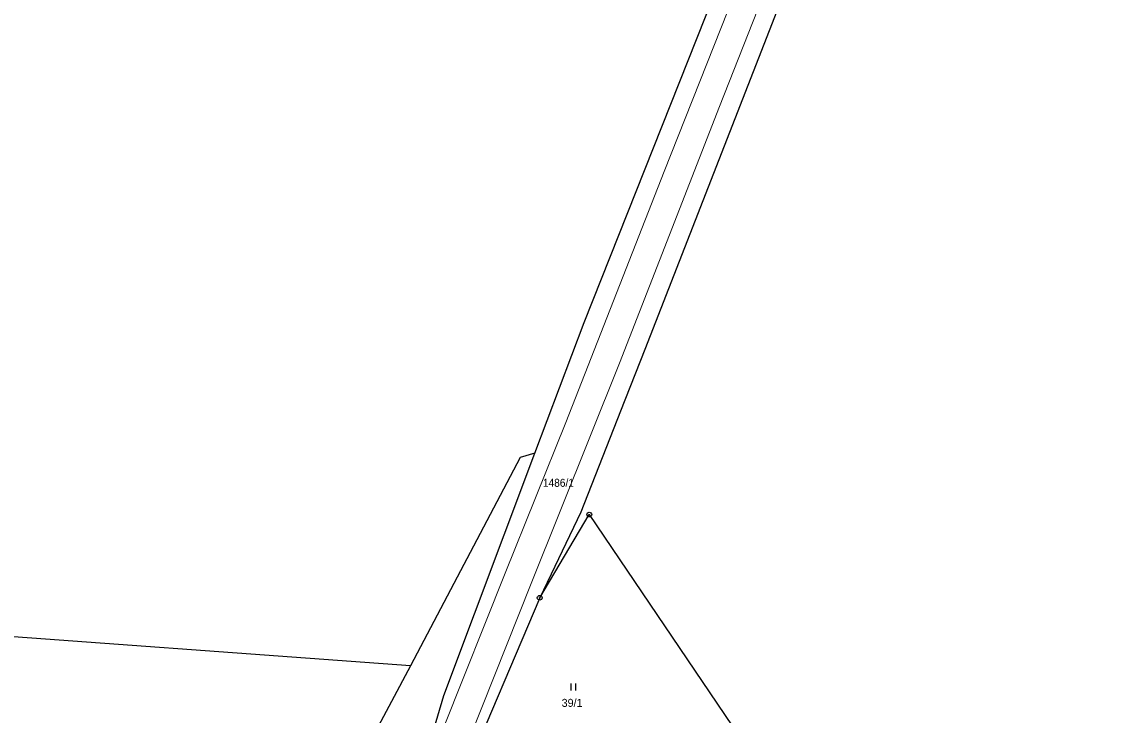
# Model space of a CAD drawing. Extents: x -872229 to -869198, y -1075981 to -1074329.
# Drawn here: x -871207 to -870978.1, y -1075083.8 to -1074936.4 of the extents above; entities that cross this region are included whole.
import ezdxf
from ezdxf.enums import TextEntityAlignment as Align

# ---------------------------------------------------------------- set-up
doc = ezdxf.new("R2010")
doc.units = 0
doc.header["$LTSCALE"] = 0.68
for name, color, linetype, lineweight in [('1', 7, 'Continuous', 25), ('3', 7, 'Continuous', 25), ('4', 7, 'Continuous', 13), ('8', 7, 'Continuous', 25)]:
    doc.layers.add(name, color=color, linetype=linetype, lineweight=lineweight)
doc.layers.add('2', color=7, linetype='Continuous')

msp = doc.modelspace()

# ---------------------------------------------------------------- linework, layer by layer
at = {"layer": '1'}
for points in [[(-870981.09, -1074678.49), (-870978.14, -1074698.51), (-870980.02, -1074733.6), (-870985.23, -1074766.42), (-870992.05, -1074792.43), (-871004.56, -1074826.1), (-871074.68, -1075006.03), (-871079.84, -1075019.17), (-871088.25, -1075040.59), (-871096.99, -1075058.79)], [(-871098, -1075028.09), (-871087.54, -1075000.31), (-871037.76, -1074874.85)], [(-871125.74, -1075108.09), (-871117.37, -1075079.56), (-871098, -1075028.09)], [(-871098, -1075028.09), (-871101.13, -1075029.01), (-871124.45, -1075073.24)], [(-871096.99, -1075058.79), (-871086.45, -1075041.13), (-871054.49, -1075088.37)], [(-871124.45, -1075073.24), (-871227.17, -1075065.71), (-871309.09, -1075059.71)], [(-871096.99, -1075058.79), (-871113.45, -1075097.58), (-871115.74, -1075103.81)], [(-871124.45, -1075073.24), (-871133.02, -1075089.5), (-871140.45, -1075111.97), (-871156.44, -1075128.18), (-871164.16, -1075134.61)]]:
    msp.add_lwpolyline(points, dxfattribs=at)
at = {"layer": '3'}
for p, q in [((-871090.311, -1075078.48), (-871090.311, -1075076.98)), ((-871089.31, -1075078.48), (-871089.31, -1075076.98))]:
    msp.add_line(p, q, dxfattribs=at)
at = {"layer": '4'}
for p, q in [((-871091.42, -1075021.56), (-871070.54, -1074968.25)), ((-871080.04, -1075008.93), (-871098.77, -1075055.79))]:
    msp.add_line(p, q, dxfattribs=at)
for points in [[(-871070.54, -1074968.25), (-871044.98, -1074903.65), (-871018.55, -1074837.46)], [(-871046.65, -1074923.52), (-871058.82, -1074954.4), (-871080.04, -1075008.93)], [(-871117.44, -1075086.44), (-871104.3, -1075053.55), (-871091.42, -1075021.56)], [(-871098.77, -1075055.79), (-871111.92, -1075088.68), (-871116.26, -1075103.1)]]:
    msp.add_lwpolyline(points, dxfattribs=at)
at = {"layer": '8'}
for centre, radius in [((-871086.45, -1075041.1299), 0.5), ((-871086.45, -1075041.1299), 0.0303), ((-871096.99, -1075058.7899), 0.5), ((-871096.99, -1075058.7899), 0.0303)]:
    msp.add_circle(centre, radius, dxfattribs=at)

# ---------------------------------------------------------------- texts
at = {"layer": '2', "width": 0.95}
msp.add_text('1486/1', height=1.7, dxfattribs=at).set_placement((-871093.009, -1075035.22), align=Align.CENTER)
at = {"layer": '2'}
msp.add_text('39/1', height=1.7, dxfattribs=at).set_placement((-871092.32, -1075081.97))

doc.saveas('drawing.dxf')
